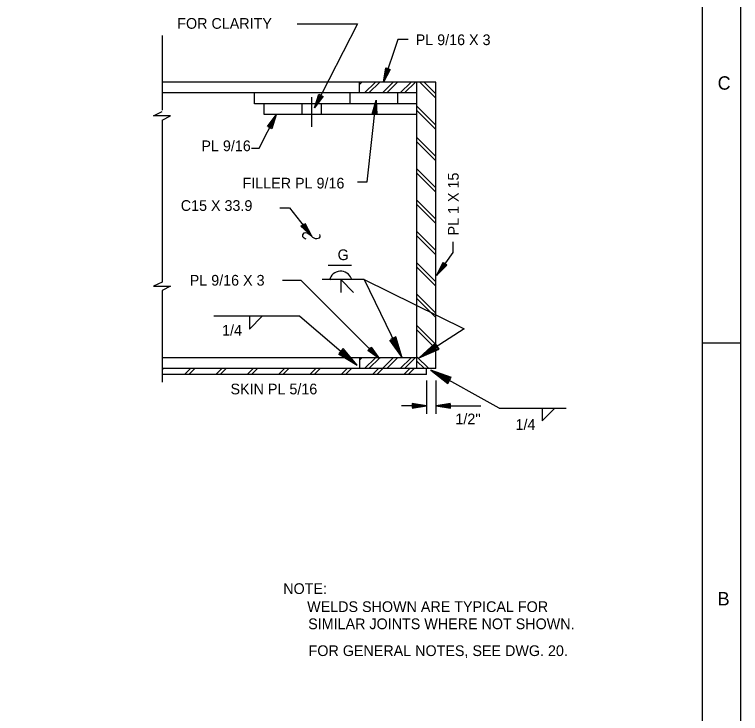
# Model space of a CAD drawing. Extents: x -0.4 to 13.5, y 0 to 9.5.
# Drawn here: x 10.291 to 13.458, y 3.175 to 6.224 of the extents above; entities that cross this region are included whole.
import ezdxf

# ---------------------------------------------------------------- set-up
doc = ezdxf.new("R2010")
doc.units = 0
for name, color, linetype in [('Level 1', 7, 'Continuous'), ('Level 13', 7, 'Continuous'), ('Level 25', 7, 'Continuous'), ('Level 3', 7, 'Continuous'), ('Level 50', 7, 'Continuous')]:
    doc.layers.add(name, color=color, linetype=linetype)

msp = doc.modelspace()

# ---------------------------------------------------------------- linework, layer by layer
at = {"layer": 'Level 1'}
msp.add_line((13.2917, 4.7917), (13.4583, 4.7917), dxfattribs=at)
for points in [[(0.125, 9.4583), (13.4583, 9.4583), (13.4583, 0.125), (0.125, 0.125)], [(0.625, 9.2917), (13.2917, 9.2917), (13.2917, 0.2917), (0.625, 0.2917)]]:
    msp.add_lwpolyline(points, close=True, dxfattribs=at)
at = {"layer": 'Level 13'}
for points in [[(10.9346, 5.7635), (10.9721, 5.7821), (10.8972, 5.7821), (10.9346, 5.8009)], [(10.9346, 5.057), (10.8971, 5.0384), (10.9721, 5.0384), (10.9346, 5.0196)]]:
    msp.add_lwpolyline(points, dxfattribs=at)
at = {"layer": 'Level 25'}
for p, q in [((10.9346, 6.1324), (10.9346, 5.8069)), ((12.1297, 5.9292), (10.9346, 5.9292)), ((11.7963, 5.8824), (11.7963, 5.9292)), ((11.8064, 5.9292), (11.7963, 5.9191)), ((11.8654, 5.9292), (11.8185, 5.8824)), ((11.8842, 5.9292), (11.8373, 5.8824)), ((11.9431, 5.9292), (11.8963, 5.8824)), ((11.962, 5.9292), (11.9151, 5.8824)), ((12.0209, 5.9292), (11.9741, 5.8824)), ((12.0398, 5.9292), (11.9929, 5.8824)), ((12.0463, 4.6792), (12.0463, 5.9292)), ((12.0596, 5.9292), (12.1297, 5.8592)), ((12.0785, 5.9292), (12.1297, 5.8781)), ((12.1297, 4.6792), (12.1297, 5.9292)), ((12.0463, 5.8824), (10.9346, 5.8824)), ((11.338, 5.8342), (11.338, 5.8824)), ((11.588, 5.7342), (11.588, 5.8631)), ((11.7547, 5.8342), (11.7547, 5.8824)), ((11.963, 5.8342), (11.963, 5.8824)), ((12.0463, 5.8342), (11.338, 5.8342)), ((11.3797, 5.7874), (11.3797, 5.8342)), ((11.5463, 5.7874), (11.5463, 5.8342)), ((11.6297, 5.7874), (11.6297, 5.8342)), ((12.0463, 5.8247), (12.1297, 5.7414)), ((12.0463, 5.8058), (12.1297, 5.7225)), ((12.0463, 5.7874), (11.3797, 5.7874)), ((10.9346, 5.7635), (10.9346, 5.057)), ((12.0463, 5.688), (12.1297, 5.6046)), ((12.0463, 5.6691), (12.1297, 5.5858)), ((12.0463, 5.5513), (12.1297, 5.4679)), ((12.0463, 5.5324), (12.1297, 5.4491)), ((12.0463, 5.4146), (12.1297, 5.3312)), ((12.0463, 5.3957), (12.1297, 5.3124)), ((12.0463, 5.2779), (12.1297, 5.1945)), ((12.0463, 5.259), (12.1297, 5.1757)), ((12.0463, 5.1412), (12.1297, 5.0578)), ((11.7607, 5.1287), (11.6597, 5.1287)), ((12.0463, 5.1223), (12.1297, 5.039)), ((11.816, 5.0677), (11.633, 5.0677)), ((11.7144, 5.0677), (11.7144, 5.0115)), ((11.7144, 5.0677), (11.7703, 5.0117)), ((11.816, 5.0677), (11.9818, 4.7265)), ((11.816, 5.0677), (12.2524, 4.8523)), ((10.9346, 5.0196), (10.9346, 4.6206)), ((12.0463, 5.0044), (12.1297, 4.9211)), ((12.0463, 4.9856), (12.1297, 4.9023)), ((11.5358, 4.9076), (11.1607, 4.9076)), ((11.3161, 4.9082), (11.3161, 4.8519)), ((11.3161, 4.8519), (11.372, 4.9078)), ((11.5358, 4.9076), (11.7855, 4.6941)), ((12.0463, 4.8677), (12.1297, 4.7844)), ((12.0463, 4.8489), (12.1297, 4.7656)), ((12.2524, 4.8523), (12.0561, 4.7265)), ((12.0463, 4.7261), (10.9346, 4.7261)), ((11.7963, 4.7261), (11.7963, 4.6792)), ((11.8063, 4.7261), (11.7963, 4.7161)), ((11.8652, 4.7261), (11.8183, 4.6792)), ((11.8841, 4.7261), (11.8372, 4.6792)), ((11.943, 4.7261), (11.8961, 4.6792)), ((11.9619, 4.7261), (11.915, 4.6792)), ((11.9704, 4.7499), (11.9704, 4.7499)), ((12.0208, 4.7261), (11.9739, 4.6792)), ((11.9818, 4.7265), (11.9818, 4.7265)), ((12.0396, 4.7261), (11.9928, 4.6792)), ((12.0463, 4.731), (12.0981, 4.6792)), ((12.0561, 4.7265), (12.0561, 4.7265)), ((12.078, 4.7405), (12.078, 4.7405)), ((11.7657, 4.7109), (11.7657, 4.7109)), ((11.7855, 4.6941), (11.7855, 4.6941)), ((12.0463, 4.7122), (12.0793, 4.6792)), ((12.1297, 4.6792), (10.9346, 4.6792)), ((10.9404, 4.6792), (10.9346, 4.6735)), ((11.0583, 4.6792), (11.0322, 4.6532)), ((11.0771, 4.6792), (11.0511, 4.6532)), ((11.195, 4.6792), (11.1689, 4.6532)), ((11.2138, 4.6792), (11.1878, 4.6532)), ((11.3317, 4.6792), (11.3056, 4.6532)), ((11.3505, 4.6792), (11.3245, 4.6532)), ((11.4684, 4.6792), (11.4423, 4.6532)), ((11.4872, 4.6792), (11.4612, 4.6532)), ((11.6051, 4.6792), (11.5791, 4.6532)), ((11.6239, 4.6792), (11.5979, 4.6532)), ((11.7418, 4.6792), (11.7158, 4.6532)), ((11.7607, 4.6792), (11.7346, 4.6532)), ((11.8785, 4.6792), (11.8525, 4.6532)), ((11.8974, 4.6792), (11.8713, 4.6532)), ((12.0152, 4.6792), (11.9892, 4.6532)), ((12.0341, 4.6792), (12.008, 4.6532)), ((12.088, 4.6532), (12.088, 4.6792)), ((12.4049, 4.5072), (12.1076, 4.6731)), ((12.1076, 4.6731), (12.1076, 4.6731)), ((12.1303, 4.6604), (12.1303, 4.6604)), ((12.088, 4.6532), (10.9346, 4.6532)), ((12.088, 4.6273), (12.088, 4.4824)), ((12.1297, 4.6273), (12.1297, 4.4824)), ((12.088, 4.5168), (11.9799, 4.5168)), ((12.131, 4.5168), (12.3249, 4.5168)), ((12.4049, 4.5072), (12.6977, 4.5072)), ((12.5924, 4.5072), (12.5924, 4.451)), ((12.5924, 4.451), (12.6483, 4.5068))]:
    msp.add_line(p, q, dxfattribs=at)
for points in [[(11.927, 4.8038), (11.9818, 4.7265), (11.9549, 4.8173), (11.931, 4.8058), (11.9704, 4.7499), (11.9521, 4.8116), (11.9368, 4.8041), (11.9595, 4.7723), (11.9494, 4.8058), (11.9431, 4.8027), (11.9481, 4.7957)], [(12.1265, 4.79), (12.0561, 4.7265), (12.1432, 4.7639), (12.1289, 4.7862), (12.078, 4.7405), (12.1372, 4.7659), (12.128, 4.7802), (12.0991, 4.754), (12.1311, 4.768), (12.1273, 4.7739), (12.121, 4.768)], [(11.7043, 4.743), (11.7855, 4.6941), (11.7245, 4.7666), (11.7073, 4.7465), (11.7657, 4.7109), (11.7243, 4.7602), (11.7132, 4.7473), (11.7467, 4.7272), (11.7241, 4.7538), (11.7195, 4.7485), (11.727, 4.7441)], [(12.1968, 4.6411), (12.1076, 4.6731), (12.1817, 4.614), (12.1946, 4.6371), (12.1303, 4.6604), (12.1806, 4.6203), (12.1889, 4.6352), (12.1521, 4.6482), (12.1796, 4.6266), (12.183, 4.6327), (12.1748, 4.6356)]]:
    msp.add_lwpolyline(points, dxfattribs=at)
msp.add_arc((11.7139, 5.0547), 0.0497, 19.8153, 167.7431, dxfattribs=at)
msp.add_spline([(11.5629, 5.2442), (11.5492, 5.2539), (11.5546, 5.2709), (11.5816, 5.2614), (11.6031, 5.2472), (11.6246, 5.2541), (11.6231, 5.2637)], degree=3, dxfattribs=at)
at = {"layer": 'Level 3'}
for p, q in [((11.9004, 5.9286), (11.9004, 5.9286)), ((11.9059, 5.945), (11.9059, 5.945)), ((11.6077, 5.8318), (11.6077, 5.8318)), ((11.8671, 5.8332), (11.8671, 5.8332)), ((11.869, 5.8504), (11.869, 5.8504)), ((11.5998, 5.8164), (11.5998, 5.8164)), ((11.4243, 5.7703), (11.4243, 5.7703)), ((11.4321, 5.7857), (11.4321, 5.7857)), ((11.5765, 5.2714), (11.5765, 5.2714)), ((11.5872, 5.2578), (11.5872, 5.2578)), ((12.1324, 5.0849), (12.1324, 5.0849)), ((12.1423, 5.0991), (12.1423, 5.0991)), ((11.8712, 4.734), (11.8712, 4.734)), ((11.8835, 4.7217), (11.8835, 4.7217))]:
    msp.add_line(p, q, dxfattribs=at)
for points in [[(11.5241, 6.1829), (11.7873, 6.1829), (11.5998, 5.8164)], [(12.0088, 6.1148), (11.9638, 6.1148), (11.9004, 5.9286)], [(11.9302, 5.9843), (11.9004, 5.9286), (11.9107, 5.9909), (11.9274, 5.9853), (11.9059, 5.945), (11.913, 5.9873), (11.9237, 5.9837), (11.9113, 5.9608), (11.9153, 5.9837), (11.9197, 5.9822), (11.9169, 5.9772)], [(11.6374, 5.8672), (11.5998, 5.8164), (11.619, 5.8766), (11.6347, 5.8685), (11.6077, 5.8318), (11.6208, 5.8727), (11.6309, 5.8675), (11.6153, 5.8466), (11.6225, 5.8688), (11.6267, 5.8667), (11.6232, 5.8621)], [(11.7869, 5.4938), (11.8288, 5.4938), (11.869, 5.8504)], [(11.8517, 5.7896), (11.869, 5.8504), (11.8723, 5.7873), (11.8547, 5.7893), (11.8671, 5.8332), (11.8693, 5.7903), (11.858, 5.7916), (11.8652, 5.8166), (11.8663, 5.7934), (11.8616, 5.7939), (11.8632, 5.7994)], [(11.3255, 5.6407), (11.3587, 5.6407), (11.4321, 5.7857)], [(11.3948, 5.7348), (11.4321, 5.7857), (11.4132, 5.7255), (11.3974, 5.7334), (11.4243, 5.7703), (11.4114, 5.7293), (11.4013, 5.7345), (11.4168, 5.7554), (11.4097, 5.7332), (11.4055, 5.7353), (11.409, 5.7399)], [(11.4481, 5.3806), (11.4911, 5.3806), (11.5872, 5.2578)], [(11.5569, 5.3132), (11.5872, 5.2578), (11.5407, 5.3005), (11.5546, 5.3114), (11.5765, 5.2714), (11.5449, 5.3004), (11.5539, 5.3074), (11.5663, 5.2846), (11.5492, 5.3004), (11.5529, 5.3033), (11.5556, 5.2982)], [(12.2029, 5.2317), (12.2029, 5.1859), (12.1324, 5.0849)], [(12.1596, 5.1419), (12.1324, 5.0849), (12.1765, 5.1301), (12.162, 5.1402), (12.1423, 5.0991), (12.1723, 5.1298), (12.163, 5.1363), (12.1518, 5.1128), (12.168, 5.1295), (12.1642, 5.1322), (12.1618, 5.127)], [(11.46, 5.0655), (11.5398, 5.0655), (11.8835, 4.7217)], [(11.8467, 4.7731), (11.8835, 4.7217), (11.8321, 4.7585), (11.8446, 4.771), (11.8712, 4.734), (11.8363, 4.7589), (11.8444, 4.767), (11.8594, 4.7457), (11.8406, 4.7594), (11.8439, 4.7627), (11.8472, 4.758)]]:
    msp.add_lwpolyline(points, dxfattribs=at)
at = {"layer": 'Level 50'}
for p, q in [((12.0707, 4.5168), (12.0707, 4.5168)), ((12.088, 4.5168), (12.088, 4.5168)), ((12.131, 4.5168), (12.131, 4.5168)), ((12.1483, 4.5168), (12.1483, 4.5168))]:
    msp.add_line(p, q, dxfattribs=at)
for points in [[(12.0257, 4.5064), (12.088, 4.5168), (12.0257, 4.5271), (12.0257, 4.5094), (12.0707, 4.5168), (12.0283, 4.5238), (12.0283, 4.5124), (12.054, 4.5168), (12.031, 4.5204), (12.031, 4.5158), (12.0367, 4.5168)], [(12.1933, 4.5271), (12.131, 4.5168), (12.1933, 4.5064), (12.1933, 4.5241), (12.1483, 4.5168), (12.1907, 4.5098), (12.1907, 4.5211), (12.165, 4.5168), (12.188, 4.5131), (12.188, 4.5178), (12.1823, 4.5168)]]:
    msp.add_lwpolyline(points, dxfattribs=at)

# ---------------------------------------------------------------- texts
at = {"layer": 'Level 1'}
for s, p in [('C', (13.3587, 5.8961)), ('B', (13.3587, 3.6461))]:
    msp.add_text(s, height=0.0584, dxfattribs=at).set_placement(p)
at = {"layer": 'Level 25'}
for s, height, p in [('FOR CLARITY', 0.046698, (11.001, 6.1618)), ('PL 9/16 X 3', 0.046698, (12.0414, 6.0905)), ('PL 9/16', 0.0467, (11.1064, 5.6278)), ('FILLER PL 9/16', 0.046698, (11.2858, 5.465)), ('C15 X 33.9', 0.0467, (11.0162, 5.3673)), ('G', 0.0467, (11.7005, 5.1525)), ('PL 9/16 X 3', 0.046698, (11.0554, 5.0412)), ('1/4', 0.0467, (11.1965, 4.8232)), ('SKIN PL 5/16', 0.046698, (11.2334, 4.5668)), ("1/2''", 0.0467, (12.2144, 4.4362)), ('1/4', 0.0467, (12.4769, 4.4119)), ('NOTE:', 0.0467, (11.4633, 3.6959)), ('WELDS SHOWN ARE TYPICAL FOR', 0.046698, (11.5677, 3.6172)), ('SIMILAR JOINTS WHERE NOT SHOWN.', 0.046698, (11.5721, 3.5423)), ('FOR GENERAL NOTES, SEE DWG. 20.', 0.046698, (11.5739, 3.4251))]:
    msp.add_text(s, height=height, dxfattribs=at).set_placement(p)
msp.add_text('PL 1 X 15', height=0.0467, rotation=90, dxfattribs=at).set_placement((12.2289, 5.2601))

doc.saveas('drawing.dxf')
